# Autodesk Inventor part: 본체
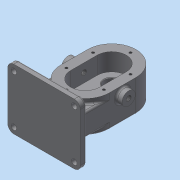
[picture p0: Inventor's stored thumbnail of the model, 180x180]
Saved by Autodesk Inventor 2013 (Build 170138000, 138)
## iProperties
Created: 2020-09
Part Number: 본체
Material: 일반
Document SubType Name: Modeling
Designer: dgall
Density: 1 g/cm^3
Author: dgall
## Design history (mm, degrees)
sketch "스케치1"
  geometry: L1 (-40, 0)-(-40, -44); L2 (40, 0)-(40, -44); A1 r 40 centre (0, 0) between (40, 0) and (-40, 0); A2 r 40 centre (0, -44) between (-40, -44) and (40, -44); 3 further points
  constraints: 5 point on circle, 4 end point, 2 centre point, 2 tangent, 1 coincident, 1 equal radius, 1 midpoint, 1 parallel, 1 vertical, 1 vertical alignment
  dimensions: "d3" = 40 radius of A1; "d5" = 44 distance of A2.centre point (0, 0)
extrude "돌출1" new body sketch "스케치1" distance "d9" = 53; taper "d10" = 0 deg
sketch "스케치2"
  geometry: C1 r 19 at (0, 0); A1 r 40 centre (0, 0) between (40, 0) and (-40, 0) reference
  constraints: 1 centre point, 1 coincident
  dimensions: "d11" = 38 diameter of C1
extrude "돌출2" join sketch "스케치2" distance "d13" = 17; taper "d14" = 0 deg
sketch "스케치3"
  geometry: L1 (-60, -102)-(60, -102); L2 (60, -102)-(60, -112); L3 (60, -112)-(-60, -112); L4 (-60, -112)-(-60, -102); A1 r 40 centre (0, 0) between (40, 0) and (-40, 0) reference; 3 further points
  constraints: 8 end point, 2 parallel, 2 point on circle, 1 coincident, 1 horizontal, 1 midpoint, 1 perpendicular, 1 vertical alignment
  dimensions: "d15" = 10 distance of L3.end L1.start; "d17" = 152 vertical distance of L3.end point (0, 40); "d18" = 120 distance of L2.end L3.end
extrude "돌출3" join sketch "스케치3" distance "d19" = 100; taper "d20" = 0 deg
node "작업 평면1"
sketch "스케치4"
  geometry: L1 (-60, -102)-(60, -102) reference; L2 (-40, -44)-(-40, -102); L3 (40, -44)-(40, -102); A1 r 40 centre (0, -44) between (-40, -44) and (40, -44) reference; 1 further point
  constraints: 4 end point, 2 perpendicular, 2 point on line, 2 tangent, 1 point on circle
  dimensions: "d22" = 80 distance between parallel lines of L3 L2
extrude "돌출4" join sketch "스케치4" distance "d23" = 37; taper "d24" = 0 deg
sketch "스케치5"
  geometry: L1 (40, 0)-(40, -44) reference; L2 (-24, 0)-(-24, -44); L3 (24, 0)-(24, -44); C1 r 12.5 at (0, 0); C2 r 12.5 at (0, -44); A1 r 40 centre (0, 0) between (40, 0) and (-40, 0) reference; A2 r 40 centre (0, -44) between (-40, -44) and (40, -44) reference; A3 r 24 centre (0, 0) between (24, 0) and (-24, 0); A4 r 24 centre (0, -44) between (-24, -44) and (24, -44)
  constraints: 4 centre point, 4 coincident, 4 end point, 4 point on circle, 2 parallel, 2 tangent, 1 equal radius
  dimensions: "d25" = 24 radius of A3; "d27" = 25 diameter of C1; "d28" = 25 diameter of C2
extrude "돌출5" cut sketch "스케치5" distance "d29" = 29; taper "d30" = 0 deg
extrude "돌출6" cut sketch "스케치5" distance "d31" = 44; taper "d32" = 0 deg
sketch "스케치6"
  geometry: L1 (19, -53)-(19, -70) reference; L2 (-19, -70)-(19, -70) reference; L3 (-19, -53)-(-19, -70) reference; L4 (-12.5, -44)-(12.5, -44) reference; L5 (8.5, -44)-(8.5, -62.7); L6 (8.5, -62.7)-(14, -62.7); L7 (14, -62.7)-(14, -69.3); L8 (14, -69.3)-(14.404, -70); L9 (8.5, -44)-(0, -44); L10 (0, -44)-(0, -70); 1 further point
  constraints: 12 end point, 2 midpoint, 2 point on line, 1 parallel, 1 perpendicular, 1 vertical
  dimensions: "d33" = 30 deg angle of L7 L8; "d36" = 7.3 vertical distance of L8.end L6.end; "d38" = 0.7 vertical distance of L8.end L7.end; "d39" = 28 diameter of L7 L10; "d40" = 17 diameter of L5 L10
revolve "회전1" sketch "스케치6" stored, may be unused: angle "d41" = 90 deg
node "작업 평면2"
sketch "스케치7"
  geometry: L1 (0, 44)-(0, 0) reference; C1 r 11 at (14, 22); 2 further points
  constraints: 2 midpoint, 1 centre point, 1 coincident, 1 horizontal alignment
  dimensions: "d43" = 14 distance from line of C1.centre L1; "d44" = 22 diameter of C1
extrude "돌출7" join sketch "스케치7" stored distance "d45" = 44; taper "d46" = 0 deg
hole "구멍1" diameter "d49" = 8.376; stored, may be unused: countersink angle "d53" = 90 deg, drill point angle "d55" = 118 deg; dims "d47" = 10, "d48" = 10, "d50" = 6, "d51" = 4, "d52" = 2, "d54" = 8
sketch "스케치8"
  geometry: L1 (24, 0)-(24, -44) reference; A1 r 24 centre (0, 0) between (24, 0) and (-24, 0) reference; A2 r 24 centre (0, -44) between (-24, -44) and (24, -44) reference; 8 further points
  constraints: 4 vertical alignment, 2 horizontal alignment, 2 midpoint, 1 coincident
  dimensions: "d56" = 31 distance of point (0, 31) A1.centre; "d57" = 31 distance of point (31, 0) A1.centre; "d58" = 31 distance of point (-31, 0) A1.centre; "d59" = 31 distance of point (0, -75) A2.centre; "d60" = 22 vertical distance of point (24, -22) point (31, 0); "d61" = 44 distance of point (31, -44) point (31, 0)
hole "구멍2" sketch "스케치8" at (0, 31), (-31, 0), (-31, -44), (0, -75), (31, -44), (31, 0) diameter "d62" = 4.134; stored, may be unused: countersink angle "d66" = 90 deg, drill point angle "d68" = 118 deg; dims "d63" = 10, "d64" = 4, "d65" = 2, "d67" = 12
fillet "모깎기1" dims "d69" = 10
sketch "스케치9"
  geometry: A1 r 10 centre (100, -10) between (110, -10) and (100, 0) reference; A2 r 10 centre (0, -10) between (0, 0) and (-10, -10) reference; A3 r 10 centre (0, -90) between (-10, -90) and (0, -100) reference; A4 r 10 centre (100, -90) between (100, -100) and (110, -90) reference; 1 further point
hole "구멍3" sketch "스케치9" at (0, -10), (0, -90), (100, -90), (100, -10) diameter "d70" = 9; stored, may be unused: countersink angle "d74" = 90 deg, drill point angle "d76" = 0 deg; dims "d71" = 10, "d72" = 4, "d73" = 2, "d75" = 12
fillet "모깎기2" dims "d77" = 0.5
fillet "모깎기3" dims "d78" = 3
fillet "모깎기4" dims "d79" = 3
fillet "모깎기7" dims "d82" = 3
chamfer "모따기1" distance "d83" = 1; stored, may be unused: second distance "d84" = 2, angle "d85" = 45 deg
sketch "스케치10"
  geometry: L1 (-10, 87)-(-10, 7) reference; L2 (0, -3)-(100, -3) reference; 2 further points
  constraints: 1 other
  dimensions: "d86" = 60 distance from line of point (50, 9) L1; "d87" = 12 distance from line of L2 point (50, 9)
feature "엠보싱1" sketch "스케치10" dims "d88" = 0.5, "d89" = 0
node "솔리드1"
mirror "대칭2"
other parameters: "d21" = -25
